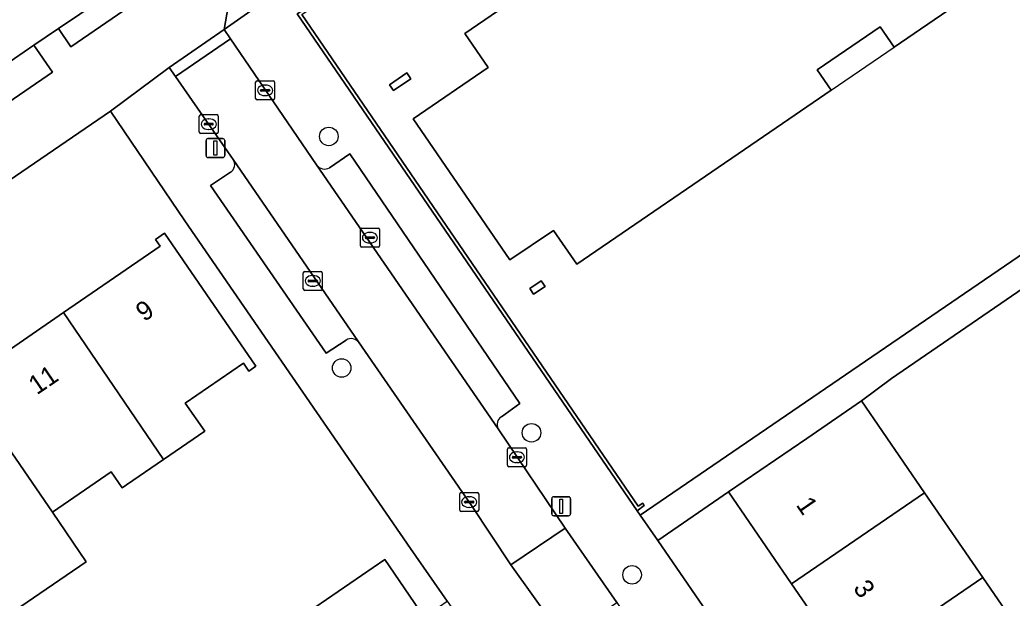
# Model space of a CAD drawing. Extents: x 157445 to 158888, y 383061 to 384688.
# Drawn here: x 158177.3 to 158229.6, y 383550.8 to 383581.3 of the extents above; entities that cross this region are included whole.
import ezdxf

# ---------------------------------------------------------------- set-up
doc = ezdxf.new("R2010")
doc.units = 0
for name, color, linetype in [('IMGEO_Boom', 7, 'Continuous'), ('IMGEO_Erf', 7, 'Continuous'), ('IMGEO_Kolk', 7, 'Continuous'), ('IMGEO_Lichtmast', 7, 'Continuous'), ('IMGEO_Muur', 7, 'Continuous'), ('IMGEO_Pand', 7, 'Continuous'), ('IMGEO_Pand_nummerreeks', 7, 'Continuous'), ('IMGEO_Pand_overbouw', 7, 'Continuous'), ('IMGEO_Parkeervlak_open', 7, 'Continuous'), ('IMGEO_Rijbaan_lokaal_open', 7, 'Continuous'), ('IMGEO_Voetpad_open', 7, 'Continuous')]:
    doc.layers.add(name, color=color, linetype=linetype)

msp = doc.modelspace()

# ---------------------------------------------------------------- linework, layer by layer
at = {"layer": 'IMGEO_Boom'}
for centre in [(158193.57, 383575.139), (158194.251, 383562.925), (158204.261, 383559.507), (158209.566, 383552.015)]:
    msp.add_circle(centre, 0.489, dxfattribs=at)
at = {"layer": 'IMGEO_Erf'}
for points in [[(158192.146, 383581.575), (158209.881, 383555.629), (158210.135, 383555.793), (158210.209, 383555.666), (158209.832, 383555.398), (158209.998, 383555.156), (158259.632, 383589.105)], [(158236.822, 383589.045), (158223.385, 383579.839), (158222.65, 383580.912), (158219.334, 383578.646), (158220.068, 383577.573), (158217.836, 383576.046), (158216.157, 383574.898), (158206.655, 383568.398), (158205.418, 383570.176), (158203.12, 383568.635), (158198.026, 383576.06), (158201.981, 383578.768), (158200.748, 383580.567), (158212.758, 383588.789)], [(158176.046, 383534.268), (158178.852, 383536.141), (158177.301, 383538.361), (158181.076, 383540.997), (158185.085, 383543.797), (158186.636, 383541.576), (158189.218, 383543.461), (158187.667, 383545.708), (158191.348, 383548.247), (158192.898, 383546), (158193.063, 383545.999), (158190.988, 383549.031), (158196.53, 383552.823), (158198.605, 383549.79), (158199.816, 383550.634), (158197.887, 383553.4), (158185.974, 383570.689), (158182.051, 383576.472), (158146.633, 383552.236)], [(158235.344, 383570.665), (158223.248, 383562.362), (158221.667, 383561.193), (158224.991, 383556.348), (158228.06, 383551.875), (158231.027, 383547.551)], [(158175.563, 383563.095), (158179.574, 383565.852), (158184.669, 383569.355), (158184.426, 383569.709), (158184.899, 383570.033), (158189.723, 383563.015), (158189.361, 383562.766), (158189.073, 383563.187), (158186, 383561.075), (158187.026, 383559.584), (158184.859, 383558.101), (158182.9, 383556.761), (158182.674, 383556.606), (158182.097, 383557.447), (158178.996, 383555.316), (158180.776, 383552.705), (158175.532, 383549.13)]]:
    msp.add_lwpolyline(points, dxfattribs=at)
for points in [[(158196.981, 383577.559), (158196.772, 383577.866), (158197.683, 383578.487), (158197.892, 383578.18)], [(158204.975, 383567.229), (158204.368, 383566.816), (158204.166, 383567.114), (158204.772, 383567.527)], [(158236.309, 383524.828), (158233.2, 383529.359), (158230.261, 383533.643), (158227.08, 383538.279), (158224.018, 383542.742), (158221.051, 383547.066), (158217.982, 383551.54), (158214.658, 383556.384), (158210.918, 383553.818), (158247.855, 383500.055), (158251.561, 383502.599), (158248.494, 383507.068), (158245.358, 383511.639), (158242.428, 383515.91), (158239.394, 383520.332)]]:
    msp.add_lwpolyline(points, close=True, dxfattribs=at)
at = {"layer": 'IMGEO_Kolk'}
for p, q in [((158189.709, 383577.144), (158189.709, 383577.996)), ((158189.784, 383578.07), (158190.636, 383578.07)), ((158190.71, 383577.996), (158190.71, 383577.144)), ((158189.968, 383577.564), (158189.968, 383577.576)), ((158190.406, 383577.527), (158190.008, 383577.527)), ((158190.011, 383577.613), (158190.409, 383577.613)), ((158190.197, 383577.85), (158190.222, 383577.85)), ((158190.452, 383577.576), (158190.452, 383577.564)), ((158190.636, 383577.07), (158189.784, 383577.07)), ((158190.22, 383577.29), (158190.195, 383577.29)), ((158186.737, 383575.361), (158186.737, 383576.213)), ((158186.812, 383576.287), (158187.664, 383576.287)), ((158186.996, 383575.781), (158186.996, 383575.793)), ((158187.039, 383575.83), (158187.437, 383575.83)), ((158187.225, 383576.067), (158187.25, 383576.067)), ((158187.48, 383575.793), (158187.48, 383575.781)), ((158187.738, 383576.213), (158187.738, 383575.361)), ((158187.664, 383575.287), (158186.812, 383575.287)), ((158187.434, 383575.744), (158187.036, 383575.744)), ((158187.248, 383575.507), (158187.223, 383575.507)), ((158195.239, 383569.372), (158195.239, 383570.224)), ((158195.314, 383570.298), (158196.166, 383570.298)), ((158195.727, 383570.078), (158195.752, 383570.078)), ((158196.24, 383570.224), (158196.24, 383569.372)), ((158195.498, 383569.792), (158195.498, 383569.804)), ((158195.936, 383569.755), (158195.538, 383569.755)), ((158195.541, 383569.841), (158195.939, 383569.841)), ((158195.75, 383569.518), (158195.725, 383569.518)), ((158195.982, 383569.804), (158195.982, 383569.792)), ((158196.166, 383569.298), (158195.314, 383569.298)), ((158192.223, 383567.093), (158192.223, 383567.945)), ((158192.298, 383568.019), (158193.15, 383568.019)), ((158193.224, 383567.945), (158193.224, 383567.093)), ((158192.482, 383567.513), (158192.482, 383567.525)), ((158192.92, 383567.476), (158192.522, 383567.476)), ((158192.525, 383567.562), (158192.923, 383567.562)), ((158192.711, 383567.799), (158192.736, 383567.799)), ((158192.966, 383567.525), (158192.966, 383567.513)), ((158193.15, 383567.019), (158192.298, 383567.019)), ((158192.734, 383567.239), (158192.709, 383567.239)), ((158202.992, 383557.792), (158202.992, 383558.644)), ((158203.067, 383558.718), (158203.919, 383558.718)), ((158203.993, 383558.644), (158203.993, 383557.792)), ((158203.251, 383558.212), (158203.251, 383558.224)), ((158203.689, 383558.175), (158203.291, 383558.175)), ((158203.294, 383558.261), (158203.692, 383558.261)), ((158203.48, 383558.498), (158203.505, 383558.498)), ((158203.735, 383558.224), (158203.735, 383558.212)), ((158203.919, 383557.718), (158203.067, 383557.718)), ((158203.503, 383557.938), (158203.478, 383557.938)), ((158200.474, 383555.427), (158200.474, 383556.279)), ((158200.549, 383556.353), (158201.401, 383556.353)), ((158200.776, 383555.896), (158201.174, 383555.896)), ((158200.962, 383556.133), (158200.987, 383556.133)), ((158201.475, 383556.279), (158201.475, 383555.427)), ((158200.733, 383555.847), (158200.733, 383555.859)), ((158201.171, 383555.81), (158200.773, 383555.81)), ((158200.985, 383555.573), (158200.96, 383555.573)), ((158201.217, 383555.859), (158201.217, 383555.847)), ((158201.401, 383555.353), (158200.549, 383555.353))]:
    msp.add_line(p, q, dxfattribs=at)
for points in [[(158189.709, 383577.144), (158189.709, 383577.996)], [(158189.784, 383578.07), (158190.636, 383578.07)], [(158190.71, 383577.996), (158190.71, 383577.144)], [(158190.636, 383577.07), (158189.784, 383577.07)], [(158186.737, 383575.361), (158186.737, 383576.213)], [(158186.812, 383576.287), (158187.664, 383576.287)], [(158187.738, 383576.213), (158187.738, 383575.361)], [(158187.664, 383575.287), (158186.812, 383575.287)], [(158195.239, 383569.372), (158195.239, 383570.224)], [(158195.314, 383570.298), (158196.166, 383570.298)], [(158196.24, 383570.224), (158196.24, 383569.372)], [(158196.166, 383569.298), (158195.314, 383569.298)], [(158192.223, 383567.093), (158192.223, 383567.945)], [(158192.298, 383568.019), (158193.15, 383568.019)], [(158193.224, 383567.945), (158193.224, 383567.093)], [(158193.15, 383567.019), (158192.298, 383567.019)], [(158202.992, 383557.792), (158202.992, 383558.644)], [(158203.067, 383558.718), (158203.919, 383558.718)], [(158203.993, 383558.644), (158203.993, 383557.792)], [(158203.919, 383557.718), (158203.067, 383557.718)], [(158200.474, 383555.427), (158200.474, 383556.279)], [(158200.549, 383556.353), (158201.401, 383556.353)], [(158201.475, 383556.279), (158201.475, 383555.427)], [(158201.401, 383555.353), (158200.549, 383555.353)]]:
    msp.add_lwpolyline(points, dxfattribs=at)
for centre, radius, start, end in [((158189.786, 383577.994), 0.0765, 91.552, 178.448), ((158189.786, 383577.994), 0.0765, 91.552, 178.448), ((158190.634, 383577.994), 0.0765, 1.552, 88.448), ((158190.634, 383577.994), 0.0765, 1.552, 88.448), ((158190.008, 383577.573), 0.0403, 85.8775, 175.7526), ((158190.005, 383577.563), 0.0366, 178.938, 274.7102), ((158190.409, 383577.57), 0.043, 264.8664, 352.4533), ((158190.413, 383577.575), 0.0386, 1.7309, 96.639), ((158189.786, 383577.146), 0.0765, 181.552, 268.448), ((158189.786, 383577.146), 0.0765, 181.552, 268.448), ((158190.634, 383577.146), 0.0765, 271.552, 358.448), ((158190.634, 383577.146), 0.0765, 271.552, 358.448), ((158186.814, 383576.211), 0.0765, 91.552, 178.448), ((158186.814, 383576.211), 0.0765, 91.552, 178.448), ((158187.036, 383575.79), 0.0403, 85.8775, 175.7526), ((158187.033, 383575.78), 0.0366, 178.938, 274.7102), ((158187.437, 383575.787), 0.043, 264.8664, 352.4533), ((158187.441, 383575.792), 0.0386, 1.7309, 96.639), ((158187.662, 383576.211), 0.0765, 1.552, 88.448), ((158187.662, 383576.211), 0.0765, 1.552, 88.448), ((158186.814, 383575.363), 0.0765, 181.552, 268.448), ((158186.814, 383575.363), 0.0765, 181.552, 268.448), ((158187.662, 383575.363), 0.0765, 271.552, 358.448), ((158187.662, 383575.363), 0.0765, 271.552, 358.448), ((158195.316, 383570.222), 0.0765, 91.552, 178.448), ((158195.316, 383570.222), 0.0765, 91.552, 178.448), ((158196.164, 383570.222), 0.0765, 1.552, 88.448), ((158196.164, 383570.222), 0.0765, 1.552, 88.448), ((158195.538, 383569.801), 0.0403, 85.8775, 175.7526), ((158195.535, 383569.791), 0.0366, 178.938, 274.7102), ((158195.939, 383569.798), 0.043, 264.8664, 352.4533), ((158195.943, 383569.803), 0.0386, 1.7309, 96.639), ((158195.316, 383569.374), 0.0765, 181.552, 268.448), ((158195.316, 383569.374), 0.0765, 181.552, 268.448), ((158196.164, 383569.374), 0.0765, 271.552, 358.448), ((158196.164, 383569.374), 0.0765, 271.552, 358.448), ((158192.3, 383567.943), 0.0765, 91.552, 178.448), ((158192.3, 383567.943), 0.0765, 91.552, 178.448), ((158193.148, 383567.943), 0.0765, 1.552, 88.448), ((158193.148, 383567.943), 0.0765, 1.552, 88.448), ((158192.522, 383567.522), 0.0403, 85.8775, 175.7526), ((158192.519, 383567.512), 0.0366, 178.938, 274.7102), ((158192.923, 383567.519), 0.043, 264.8664, 352.4533), ((158192.927, 383567.524), 0.0386, 1.7309, 96.639), ((158192.3, 383567.095), 0.0765, 181.552, 268.448), ((158192.3, 383567.095), 0.0765, 181.552, 268.448), ((158193.148, 383567.095), 0.0765, 271.552, 358.448), ((158193.148, 383567.095), 0.0765, 271.552, 358.448), ((158203.069, 383558.642), 0.0765, 91.552, 178.448), ((158203.069, 383558.642), 0.0765, 91.552, 178.448), ((158203.917, 383558.642), 0.0765, 1.552, 88.448), ((158203.917, 383558.642), 0.0765, 1.552, 88.448), ((158203.291, 383558.221), 0.0403, 85.8775, 175.7526), ((158203.288, 383558.211), 0.0366, 178.938, 274.7102), ((158203.692, 383558.218), 0.043, 264.8664, 352.4533), ((158203.696, 383558.223), 0.0386, 1.7309, 96.639), ((158203.069, 383557.794), 0.0765, 181.552, 268.448), ((158203.069, 383557.794), 0.0765, 181.552, 268.448), ((158203.917, 383557.794), 0.0765, 271.552, 358.448), ((158203.917, 383557.794), 0.0765, 271.552, 358.448), ((158200.551, 383556.277), 0.0765, 91.552, 178.448), ((158200.551, 383556.277), 0.0765, 91.552, 178.448), ((158200.773, 383555.856), 0.0403, 85.8775, 175.7526), ((158201.178, 383555.858), 0.0386, 1.7309, 96.639), ((158201.399, 383556.277), 0.0765, 1.552, 88.448), ((158201.399, 383556.277), 0.0765, 1.552, 88.448), ((158200.551, 383555.429), 0.0765, 181.552, 268.448), ((158200.551, 383555.429), 0.0765, 181.552, 268.448), ((158200.77, 383555.846), 0.0366, 178.938, 274.7102), ((158201.174, 383555.853), 0.043, 264.8664, 352.4533), ((158201.399, 383555.429), 0.0765, 271.552, 358.448), ((158201.399, 383555.429), 0.0765, 271.552, 358.448)]:
    msp.add_arc(centre, radius, start, end, dxfattribs=at)
for centre, major_axis, ratio, start_param, end_param in [((158190.196, 383577.57), (-0.387, 0.002), 0.722429, 4.712389, 7.853982), ((158190.221, 383577.57), (-0.39, 0.002), 0.717154, 1.570796, 4.712389), ((158187.224, 383575.787), (-0.387, 0.002), 0.722429, 4.712389, 7.853982), ((158187.249, 383575.787), (-0.39, 0.002), 0.717154, 1.570796, 4.712389), ((158195.726, 383569.798), (-0.387, 0.002), 0.722429, 4.712389, 7.853982), ((158195.751, 383569.798), (-0.39, 0.002), 0.717154, 1.570796, 4.712389), ((158192.71, 383567.519), (-0.387, 0.002), 0.722429, 4.712389, 7.853982), ((158192.735, 383567.519), (-0.39, 0.002), 0.717154, 1.570796, 4.712389), ((158203.479, 383558.218), (-0.387, 0.002), 0.722429, 4.712389, 7.853982), ((158203.504, 383558.218), (-0.39, 0.002), 0.717154, 1.570796, 4.712389), ((158200.961, 383555.853), (-0.387, 0.002), 0.722429, 4.712389, 7.853982), ((158200.986, 383555.853), (-0.39, 0.002), 0.717154, 1.570796, 4.712389)]:
    msp.add_ellipse(centre, major_axis=major_axis, ratio=ratio, start_param=start_param, end_param=end_param, dxfattribs=at)
at = {"layer": 'IMGEO_Lichtmast'}
for p, q in [((158187.094, 383574.126), (158187.094, 383574.926)), ((158187.094, 383574.926), (158187.094, 383574.126)), ((158187.194, 383575.026), (158187.984, 383575.026)), ((158187.984, 383575.026), (158187.194, 383575.026)), ((158188.084, 383574.926), (158188.084, 383574.126)), ((158188.084, 383574.126), (158188.084, 383574.926)), ((158187.984, 383574.026), (158187.194, 383574.026)), ((158187.194, 383574.026), (158187.984, 383574.026)), ((158205.33, 383555.23), (158205.33, 383556.03)), ((158205.33, 383556.03), (158205.33, 383555.23)), ((158205.43, 383556.13), (158206.22, 383556.13)), ((158206.22, 383556.13), (158205.43, 383556.13)), ((158206.32, 383556.03), (158206.32, 383555.23)), ((158206.32, 383555.23), (158206.32, 383556.03)), ((158206.22, 383555.13), (158205.43, 383555.13)), ((158205.43, 383555.13), (158206.22, 383555.13))]:
    msp.add_line(p, q, dxfattribs=at)
for points in [[(158187.514, 383574.901), (158187.664, 383574.901), (158187.664, 383574.151), (158187.514, 383574.151), (158187.514, 383574.901)], [(158205.75, 383556.005), (158205.9, 383556.005), (158205.9, 383555.255), (158205.75, 383555.255), (158205.75, 383556.005)]]:
    msp.add_lwpolyline(points, dxfattribs=at)
for centre, start, end in [((158187.194, 383574.926), 90, 180), ((158187.194, 383574.926), 90, 180), ((158187.984, 383574.926), 0, 90), ((158187.984, 383574.926), 360, 90), ((158187.194, 383574.126), 180, 270), ((158187.194, 383574.126), 180, 270), ((158187.984, 383574.126), 270, 0), ((158187.984, 383574.126), 270, 0), ((158205.43, 383556.03), 90, 180), ((158205.43, 383556.03), 90, 180), ((158206.22, 383556.03), 0, 90), ((158206.22, 383556.03), 360, 90), ((158205.43, 383555.23), 180, 270), ((158205.43, 383555.23), 180, 270), ((158206.22, 383555.23), 270, 0), ((158206.22, 383555.23), 270, 0)]:
    msp.add_arc(centre, 0.1, start, end, dxfattribs=at)
at = {"layer": 'IMGEO_Muur'}
msp.add_lwpolyline([(158191.909, 383581.602), (158209.832, 383555.398), (158210.209, 383555.666), (158210.135, 383555.793), (158209.881, 383555.629), (158192.146, 383581.575), (158193.385, 383582.412), (158193.29, 383582.542), (158193.198, 383582.481)], close=True, dxfattribs=at)
for points in [[(158182.051, 383576.472), (158185.974, 383570.689)], [(158185.974, 383570.689), (158197.887, 383553.4)]]:
    msp.add_lwpolyline(points, dxfattribs=at)
at = {"layer": 'IMGEO_Pand'}
msp.add_lwpolyline([(158212.758, 383588.789), (158200.748, 383580.567), (158201.981, 383578.768), (158198.026, 383576.06), (158203.12, 383568.635), (158205.418, 383570.176), (158206.655, 383568.398), (158216.157, 383574.898), (158217.836, 383576.046), (158220.068, 383577.573), (158219.334, 383578.646), (158222.65, 383580.912), (158223.385, 383579.839), (158236.822, 383589.045)], dxfattribs=at)
for points in [[(158196.981, 383577.559), (158197.892, 383578.18), (158197.683, 383578.487), (158196.772, 383577.866)], [(158179.574, 383565.852), (158184.859, 383558.101), (158187.026, 383559.584), (158186, 383561.075), (158189.073, 383563.187), (158189.361, 383562.766), (158189.723, 383563.015), (158184.899, 383570.033), (158184.426, 383569.709), (158184.669, 383569.355)], [(158204.975, 383567.229), (158204.772, 383567.527), (158204.166, 383567.114), (158204.368, 383566.816)], [(158179.574, 383565.852), (158175.563, 383563.095), (158174.368, 383562.274), (158174.263, 383562.195), (158178.996, 383555.316), (158182.097, 383557.447), (158182.674, 383556.606), (158182.9, 383556.761), (158184.859, 383558.101)], [(158174.263, 383562.195), (158173.668, 383561.786), (158169.063, 383558.62), (158174.327, 383550.898), (158175.532, 383549.13), (158180.776, 383552.705), (158178.996, 383555.316)], [(158217.982, 383551.54), (158224.991, 383556.348), (158221.667, 383561.193), (158218.781, 383559.213), (158214.658, 383556.384)], [(158217.982, 383551.54), (158221.051, 383547.066), (158228.06, 383551.875), (158224.991, 383556.348)], [(158193.063, 383545.999), (158198.605, 383549.79), (158196.53, 383552.823), (158190.988, 383549.031)], [(158231.027, 383547.551), (158228.06, 383551.875), (158221.051, 383547.066), (158224.018, 383542.742)]]:
    msp.add_lwpolyline(points, close=True, dxfattribs=at)
at = {"layer": 'IMGEO_Pand_overbouw'}
msp.add_lwpolyline([(158223.385, 383579.839), (158222.65, 383580.912), (158219.334, 383578.646), (158220.068, 383577.573)], close=True, dxfattribs=at)
at = {"layer": 'IMGEO_Parkeervlak_open'}
msp.add_lwpolyline([(158174.425, 383577.495), (158155.655, 383564.619), (158156.649, 383563.194), (158178.989, 383578.53), (158178.018, 383579.96)], close=True, dxfattribs=at)
for points in [[(158202.673, 383560.349), (158203.654, 383561.055), (158194.672, 383574.228), (158193.61, 383573.485)], [(158195.138, 383564.303), (158188.531, 383573.926)], [(158188.38, 383573.254), (158187.332, 383572.553), (158193.428, 383563.713), (158194.487, 383564.401)], [(158192.925, 383573.642), (158202.497, 383559.714)]]:
    msp.add_lwpolyline(points, dxfattribs=at)
for centre, radius, start, end in [((158188.127, 383573.664), 0.481, 301.6482, 33.0235), ((158193.356, 383573.948), 0.528, 215.4011, 298.7808), ((158194.752, 383563.953), 0.52, 42.2078, 120.6704), ((158202.929, 383559.936), 0.486, 121.8315, 207.1855)]:
    msp.add_arc(centre, radius, start, end, dxfattribs=at)
at = {"layer": 'IMGEO_Rijbaan_lokaal_open'}
for points in [[(158237.43, 383620.603), (158234.147, 383625.328), (158231.951, 383623.767), (158221.121, 383616.287), (158220.994, 383616.167), (158220.784, 383615.999), (158213.207, 383610.143), (158213.02, 383609.994), (158212.903, 383609.916), (158212.744, 383609.828), (158212.721, 383609.818), (158172.026, 383581.665), (158171.879, 383581.534), (158171.721, 383581.416), (158174.425, 383577.495), (158178.018, 383579.96), (158179.317, 383580.832), (158188.368, 383586.938), (158188.489, 383587.021)], [(158203.165, 383552.542), (158206.041, 383554.471), (158202.497, 383559.714), (158192.925, 383573.642), (158188.388, 383580.295), (158185.481, 383578.308), (158188.531, 383573.926), (158195.138, 383564.303), (158201.101, 383555.663)], [(158203.165, 383552.542), (158205.555, 383549.21), (158205.896, 383548.647), (158208.763, 383550.561), (158206.041, 383554.471)]]:
    msp.add_lwpolyline(points, close=True, dxfattribs=at)
at = {"layer": 'IMGEO_Voetpad_open'}
for points in [[(158188.489, 383587.021), (158188.368, 383586.938), (158188.974, 383586.056), (158188.059, 383580.776), (158192.324, 383583.788), (158207.907, 383594.462), (158215.538, 383599.669), (158239.233, 383615.894)], [(158259.632, 383589.105), (158209.998, 383555.156), (158210.918, 383553.818), (158214.658, 383556.384), (158218.781, 383559.213), (158221.667, 383561.193), (158223.248, 383562.362), (158235.344, 383570.665), (158237.397, 383572.074), (158240.745, 383567.155), (158241.475, 383566.082), (158243.796, 383562.672), (158246.015, 383559.412), (158247.475, 383557.268), (158249.793, 383553.861), (158252.955, 383549.214), (158253.688, 383548.138), (158255.88, 383544.918), (158258.239, 383541.451)], [(158210.918, 383553.818), (158209.998, 383555.156), (158209.832, 383555.398), (158191.909, 383581.602), (158193.198, 383582.481), (158193.094, 383582.665), (158192.324, 383583.788), (158188.059, 383580.776), (158188.388, 383580.295), (158192.925, 383573.642)], [(158188.531, 383573.926), (158185.481, 383578.308), (158185.149, 383578.774), (158182.051, 383576.472), (158185.974, 383570.689), (158197.887, 383553.4), (158199.816, 383550.634), (158200.694, 383549.375), (158201.824, 383547.755), (158202.728, 383546.459), (158238.846, 383493.685), (158239.489, 383492.745), (158253.494, 383472.281), (158252.756, 383471.75), (158253.873, 383470.093), (158264.622, 383454.147), (158268.319, 383448.776), (158272.122, 383443.31), (158276.032, 383446.18), (158275.722, 383446.662), (158273.468, 383449.96)], [(158193.61, 383573.485), (158194.672, 383574.228), (158203.654, 383561.055), (158202.673, 383560.349)], [(158194.487, 383564.401), (158193.428, 383563.713), (158187.332, 383572.553), (158188.38, 383573.254)], [(158205.555, 383549.21), (158203.165, 383552.542), (158201.101, 383555.663), (158195.138, 383564.303)], [(158202.497, 383559.714), (158206.041, 383554.471), (158208.763, 383550.561), (158209.025, 383550.161)], [(158276.3, 383451.789), (158278.532, 383448.573), (158278.889, 383448.114), (158282.772, 383450.584), (158279.13, 383455.982), (158275.404, 383461.42), (158273.585, 383464.075), (158266.135, 383475.301), (158264.491, 383477.795), (158264.125, 383477.532), (158263.225, 383478.825), (158261.869, 383479.658), (158248.726, 383498.787), (158247.855, 383500.055), (158210.918, 383553.818)]]:
    msp.add_lwpolyline(points, dxfattribs=at)
for points in [[(158188.368, 383586.938), (158179.317, 383580.832), (158179.967, 383579.872), (158188.974, 383586.056)], [(158145.517, 383551.473), (158146.633, 383552.236), (158182.051, 383576.472), (158185.149, 383578.774), (158188.059, 383580.776), (158188.974, 383586.056), (158179.967, 383579.872), (158179.317, 383580.832), (158178.018, 383579.96), (158178.989, 383578.53), (158156.649, 383563.194), (158153.626, 383561.133), (158153.534, 383561.259), (158149.836, 383558.736), (158147.366, 383556.977), (158144.483, 383554.996), (158111.298, 383532.192), (158079.99, 383510.832), (158076.698, 383508.583), (158076.767, 383508.469), (158073.599, 383506.286), (158069.597, 383499.52), (158070.298, 383500)], [(158185.481, 383578.308), (158188.388, 383580.295), (158188.059, 383580.776), (158185.149, 383578.774)]]:
    msp.add_lwpolyline(points, close=True, dxfattribs=at)
for centre, radius, start, end in [((158188.127, 383573.664), 0.481, 301.6482, 33.0235), ((158193.356, 383573.948), 0.528, 215.4011, 298.7808), ((158194.752, 383563.953), 0.52, 42.2078, 120.6704), ((158202.929, 383559.936), 0.486, 121.8315, 207.1855)]:
    msp.add_arc(centre, radius, start, end, dxfattribs=at)

# ---------------------------------------------------------------- texts
at = {"layer": 'IMGEO_Pand_nummerreeks'}
for s, rotation, p in [('9', 34.2816, (158183.831, 383565.336)), ('11', 34.2801, (158178.171, 383561.477)), ('1', 304.4548, (158218.182, 383555.702)), ('3', 304.4548, (158221.193, 383551.314))]:
    msp.add_text(s, height=1, rotation=rotation, dxfattribs=at).set_placement(p)

doc.saveas('drawing.dxf')
